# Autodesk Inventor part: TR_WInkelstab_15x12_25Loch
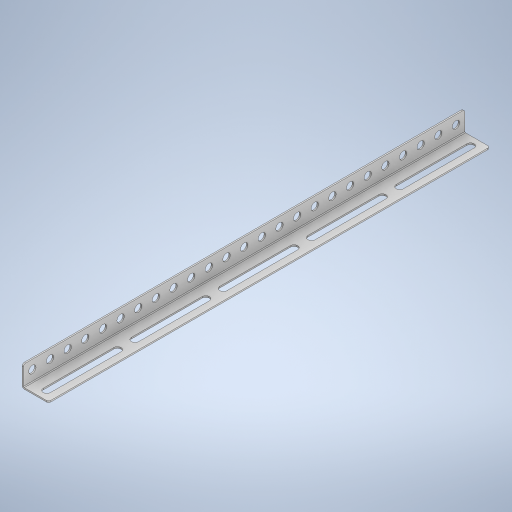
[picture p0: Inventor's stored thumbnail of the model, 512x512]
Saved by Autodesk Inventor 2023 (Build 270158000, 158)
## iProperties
Created: 2023-11
Part Number: TR_WInkelstab_15x12_25Loch
Material: Generisch
Document SubType Name: Modeling
Designer: Administrator
Density: 1 g/cm^3
Appearance: Vorgabe
Author: Administrator
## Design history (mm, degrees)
sketch "Skizze1"
  geometry: L1 (0, 12)-(0, 1.25); L2 (1.25, 0)-(15, 0); L3 (15, 0)-(15, 0.8); L4 (15, 0.8)-(1.25, 0.8); L5 (0.8, 1.25)-(0.8, 12); L6 (0.8, 12)-(0, 12); A1 r 1.25 centre (1.25, 1.25) between (0, 1.25) and (1.25, 0); A2 r 0.45 centre (1.25, 1.25) between (0.8, 1.25) and (1.25, 0.8); 1 further point
  constraints: 12 end point, 5 perpendicular, 4 point on circle, 4 tangent, 2 centre point, 2 point on line, 1 coincident, 1 vertical
  dimensions: "d0" = 1.25 radius of A1; "d2" = 0.8 distance of L5.end L1.start (= Dicke); "d3" = 12 distance of point (0, 0) L1.start; "d4" = 15 distance of point (0, 0) L2.end
extrude "Extrusion1" new body sketch "Skizze1" stored distance "d5" = 250 (computed from Lochzahl, Einheitsmaß); taper "d6" = 0 deg
sketch "Skizze2"
  geometry: L1 (7.75, 5)-(7.75, 45); L2 (9.825, 5)-(9.825, 45); L3 (5.675, 45)-(5.675, 5); L4 (13.75, 250)-(13.75, 0) reference; L5 (13.75, 0)-(0, 0) reference; A1 r 2.075 centre (7.75, 5) between (5.675, 5) and (9.825, 5); A2 r 2.075 centre (7.75, 45) between (9.825, 45) and (5.675, 45); 3 further points
  constraints: 8 end point, 4 point on circle, 4 tangent, 2 centre point, 2 midpoint, 1 parallel, 1 vertical
  dimensions: "d8" = 4.15 diameter of A2 (= 2 x Radius); "d9" = 40 distance of L1.start L1.end (= Langloch); "d10" = 6 distance from line of L4 L1.start; "d11" = 5 vertical distance of point (6.875, 0) L1.start (= 0.5 x Einheitsmaß)
extrude "Extrusion2" cut sketch "Skizze2" extent not by distance; stored distance "d12" = 0; taper "d13" = 0 deg
sketch "Skizze3"
  geometry: L1 (0, 10.75)-(250, 10.75) reference; L2 (0, 0)-(0, 10.75) reference; C1 r 2.075 at (5, 5.75); 1 further point
  constraints: 1 centre point
  dimensions: "d14" = 4.15 diameter of C1 (= 2 x Radius); "d15" = 5 distance from line of C1.centre L1 (= 0.5 x Einheitsmaß); "d16" = 5 distance from line of C1.centre L2 (= 0.5 x Einheitsmaß)
extrude "Extrusion3" cut sketch "Skizze3" extent not by distance; stored distance "d17" = 0; taper "d18" = 0 deg
fillet "Rundung1" dims "d22" = 1.25
pattern_linear "Rechteckige Anordnung2" dims "d25" = 50 (computed from Einheitsmaß, Lochzahl)
node "Volumenkörper1"
pattern_linear "Rechteckige Anordnung1" dims "d21" = 10 (= Einheitsmaß)
other parameters: "Einheitsmaß" = 10 [user parameter; used in 6 equation terms], "Radius" = 2.075 [user parameter; used in 2 equation terms], "Fasen" = 0.5 [user parameter], "Dicke" = 0.8 [user parameter; used in 1 equation term], "Breitloch" = 2 [user parameter], "Langloch" = 40 [user parameter; used in 1 equation term], "AchteckUmkreis" = 6 [user parameter], "DAchsAufnahme" = 4.1 [user parameter], "AchsDurchmesser" = 4 [user parameter], "AchsFase" = 0.5 [user parameter]
